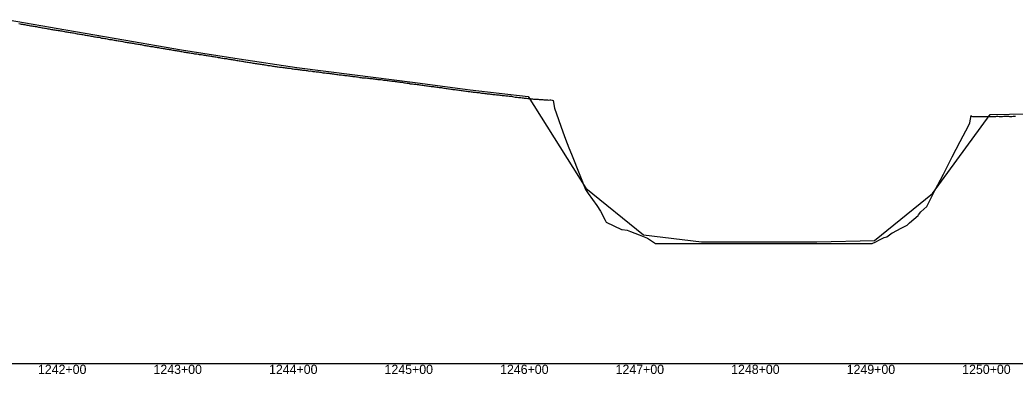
# Model space of a CAD drawing. Extents: x -3793 to 50787, y -1075 to 6138.
# Drawn here: x 11538 to 12399, y 2991 to 3298 of the extents above; entities that cross this region are included whole.
import ezdxf

# ---------------------------------------------------------------- set-up
doc = ezdxf.new("R2010")
doc.units = 0
for name, color, linetype in [('RD_DDB_Profile_EX', 7, 'Continuous'), ('RD_DDB_Profile_PR', 7, 'Continuous'), ('RD_DDB_StaTX', 7, 'Continuous'), ('RD_GPK_Profile_Cell', 7, 'Continuous')]:
    doc.layers.add(name, color=color, linetype=linetype)

msp = doc.modelspace()

# ---------------------------------------------------------------- linework, layer by layer
at = {"layer": 'RD_DDB_Profile_EX'}
for points in [[(11536.652242, 3294.36991), (11537.652092, 3294.15), (11538.655829, 3293.91986), (11539.653933, 3293.79005), (11540.652812, 3293.67002), (11541.654813, 3293.529805), (11542.647632, 3293.279725), (11543.645738, 3293.1), (11544.645586, 3292.95), (11545.649322, 3292.8), (11546.647428, 3292.579775), (11547.725313, 3292.45997), (11548.728588, 3292.21982), (11549.728712, 3292.11989), (11550.72806, 3291.910005), (11551.726314, 3291.729955), (11552.728804, 3291.60999), (11553.728931, 3291.429955), (11554.728272, 3291.23992), (11555.719036, 3291.03996), (11556.721522, 3290.82999), (11557.721653, 3290.66988), (11558.719903, 3290.5), (11559.722391, 3290.320045), (11560.72252, 3290.06035), (11561.721859, 3289.980345), (11562.720098, 3289.9), (11563.722584, 3289.6404), (11564.722715, 3289.4), (11565.722048, 3289.31019), (11566.720278, 3289.09084), (11567.723568, 3288.90076), (11568.715444, 3288.81015), (11569.713679, 3288.75), (11570.716163, 3288.480405), (11571.716296, 3288.340675), (11572.715628, 3288.1409), (11573.713853, 3287.990975), (11574.716335, 3287.78979), (11576.009865, 3287.46152), (11577.002754, 3287.35114), (11578.003685, 3287.230535), (11579.007399, 3287.070245), (11579.999286, 3286.93036), (11581.001219, 3286.78014), (11582.000125, 3286.57021), (11583.003839, 3286.38014), (11583.999548, 3286.239815), (11584.997659, 3286.12992), (11586.001373, 3285.86983), (11587.00028, 3285.65997), (11587.996928, 3285.56971), (11588.9941, 3285.24949), (11589.997814, 3285.08936), (11590.993506, 3284.97924), (11591.991634, 3284.81953), (11592.994412, 3284.688925), (11593.994254, 3284.429295), (11594.990866, 3284.3), (11595.991959, 3284.0096), (11596.991788, 3283.959635), (11597.987464, 3283.728615), (11598.987293, 3283.6), (11599.988407, 3283.46905), (11600.999406, 3283.3), (11601.993282, 3282.997275), (11602.996052, 3282.928255), (11603.995902, 3282.640545), (11604.998672, 3282.60942), (11605.99131, 3282.487575), (11606.99408, 3282.28743), (11607.995203, 3281.83723), (11608.987813, 3281.78713), (11609.990596, 3281.686985), (11610.990433, 3281.514975), (11611.993217, 3281.436985), (11612.984945, 3281.155455), (11613.988588, 3280.91837), (11614.989754, 3280.727405), (11615.989577, 3280.62751), (11616.985112, 3280.55), (11617.984083, 3280.27739), (11618.987732, 3280.14093), (11619.98325, 3279.92692), (11620.491182, 3279.8138)], [(11620.491182, 3279.8138), (11621.485517, 3279.705245), (11622.485183, 3279.522975), (11623.485443, 3279.41809), (11624.487798, 3279.29099), (11625.488058, 3279.1), (11626.480621, 3278.891065), (11627.480287, 3278.62697), (11628.483236, 3278.40893), (11629.482902, 3278.28202), (11630.48585, 3278.05893), (11631.477474, 3278), (11632.475392, 3277.767945), (11633.47834, 3277.658915), (11634.478006, 3277.45), (11635.480954, 3277.3), (11636.48062, 3277.15897), (11637.474933, 3276.976615), (11638.473444, 3276.8), (11639.475811, 3276.65886), (11640.476058, 3276.508895), (11641.478425, 3276.35), (11642.470035, 3276.14688), (11643.470289, 3275.9), (11644.470916, 3275.73536), (11645.471163, 3275.541125), (11646.425702, 3275.4), (11647.424086, 3275.258845), (11648.418672, 3275.126075), (11649.417069, 3274.873855), (11650.420344, 3274.682685), (11651.419426, 3274.55), (11652.421093, 3274.441405), (11653.411748, 3274.28289), (11654.410832, 3274.05856), (11655.414116, 3273.91701), (11656.413202, 3273.71702), (11657.414909, 3273.60844), (11658.405557, 3273.458405), (11659.407955, 3273.10832), (11660.407939, 3273.05), (11661.409684, 3272.85829), (11662.408773, 3272.68341), (11663.241396, 3272.55834), (11663.748903, 3272.508235), (11664.742062, 3272.35), (11665.744382, 3272.174375), (11666.742619, 3271.94185), (11667.745755, 3271.858065), (11668.740776, 3271.71588), (11669.740418, 3271.515955), (11670.743565, 3271.342105), (11671.741818, 3271.2), (11672.737609, 3270.97666), (11673.735871, 3270.842195), (11674.739634, 3270.66899), (11675.742809, 3270.561645), (11676.733682, 3270.254165), (11677.73612, 3270.131825), (11678.735139, 3270.05449), (11679.738909, 3269.76987), (11680.730504, 3269.675155), (11681.732966, 3269.39805), (11682.73545, 3269.333775), (11683.728297, 3269.09875), (11684.730786, 3268.984665), (11685.729083, 3268.86985), (11686.732307, 3268.699535), (11687.723139, 3268.442325), (11688.727609, 3268.26466), (11689.730143, 3268.1295), (11690.728453, 3268.079225), (11691.724199, 3267.951385), (11692.722517, 3267.74422), (11693.726294, 3267.63079), (11694.725297, 3267.523725), (11695.735083, 3267.268225), (11696.738749, 3267.0756), (11697.737703, 3266.96823), (11698.741369, 3266.73913), (11699.73146, 3266.652765), (11700.735125, 3266.52991), (11701.73408, 3266.336505), (11702.730059, 3266.1), (11703.212794, 3266.086715), (11704.215852, 3265.9), (11705.215409, 3265.830075), (11706.210078, 3265.65427), (11707.208375, 3265.517125), (11708.211433, 3265.273905), (11709.21145, 3265.123755), (11710.205647, 3264.93707), (11711.208694, 3264.743585), (11712.207014, 3264.587085), (11713.201647, 3264.430955), (11714.201215, 3264.2372), (11715.204263, 3264.17461), (11716.202595, 3264.02444), (11717.197216, 3263.831155), (11718.199829, 3263.587515), (11719.199831, 3263.48744)], [(11719.199831, 3263.48744), (11720.192787, 3263.33765), (11721.192784, 3263.18136), (11722.195402, 3262.969125), (11723.195399, 3262.887575), (11724.18836, 3262.64389), (11725.191411, 3262.5), (11726.190975, 3262.44389), (11727.194026, 3262.251545), (11728.183933, 3262.069795), (11729.186984, 3261.88203), (11730.186548, 3261.78792), (11731.181087, 3261.626275), (11732.18372, 3261.376435), (11733.182557, 3261.18223), (11734.185608, 3261.026515), (11735.176647, 3260.88241), (11736.179689, 3260.738375), (11737.181215, 3260.621175), (11738.172633, 3260.421275), (11739.175279, 3260.215765), (11740.175249, 3260.071275), (11741.176793, 3259.838605), (11742.168193, 3259.72729), (11743.170844, 3259.627445), (11744.257976, 3259.45517), (11745.25965, 3259.311105), (11746.254321, 3259.17822), (11747.25707, 3258.983785), (11748.251699, 3258.83412), (11749.244917, 3258.67926), (11750.186584, 3258.54486), (11751.182493, 3258.37989), (11752.185762, 3258.24003), (11753.181158, 3258.1), (11754.189346, 3257.995265), (11755.184726, 3257.84537), (11756.188035, 3257.627055), (11757.183844, 3257.47763), (11758.179187, 3257.336895), (11759.182516, 3257.195675), (11760.17785, 3256.995785), (11761.181601, 3256.94167), (11762.176205, 3256.78785), (11763.179569, 3256.64199), (11764.175272, 3256.530555), (11765.170566, 3256.388665), (11766.17395, 3256.242535), (11767.169587, 3256.1), (11768.172984, 3255.989295), (11769.168246, 3255.796545), (11770.171991, 3255.73979), (11771.167232, 3255.68684), (11772.170658, 3255.49027), (11773.166192, 3255.290635), (11774.160866, 3255.187985), (11775.164321, 3254.99409), (11776.16413, 3254.93906), (11777.167879, 3254.88928), (11778.16307, 3254.69231), (11779.16657, 3254.54246), (11780.161983, 3254.35), (11781.165496, 3254.29532), (11782.160653, 3254.19556), (11783.155995, 3254.041625), (11784.159529, 3253.9857), (11785.154644, 3253.792315), (11786.158049, 3253.64255), (11787.153162, 3253.44652), (11788.156736, 3253.29494), (11789.151989, 3253.339085), (11790.155577, 3253.190965), (11791.150655, 3253.043095), (11792.145712, 3252.94498), (11792.82433, 3252.842925), (11793.823599, 3252.74382), (11794.826851, 3252.642915), (11795.821132, 3252.543695), (11796.824393, 3252.44303), (11797.814388, 3252.19315), (11798.811602, 3251.94908), (11799.815098, 3251.8), (11800.805443, 3251.797465), (11801.809036, 3251.74528), (11802.812777, 3251.595625), (11803.807857, 3251.44581), (11804.806695, 3251.394775), (11805.810373, 3251.147015), (11806.805347, 3251.04814), (11807.804278, 3250.947395), (11808.807932, 3250.79676), (11809.802975, 3250.698005), (11810.80671, 3250.49835), (11811.80557, 3250.298675), (11812.800558, 3250.2488), (11813.804268, 3250.14857), (11814.803163, 3250.04821), (11815.798135, 3249.94966), (11816.994233, 3249.771255), (11817.805974, 3249.649865), (11818.796227, 3249.549815)], [(11818.796227, 3249.549815), (11819.800405, 3249.499605), (11820.80459, 3249.34936), (11821.794854, 3249.199295), (11822.79903, 3249.049255), (11823.795047, 3248.898995), (11824.799213, 3248.798845), (11825.797665, 3248.64899), (11826.793666, 3248.54848), (11827.797855, 3248.44831), (11828.796282, 3248.348645), (11829.792316, 3248.198515), (11830.796442, 3248.04838), (11831.794906, 3247.848725), (11832.790946, 3247.798465), (11833.795092, 3247.549175), (11834.36085, 3247.54765), (11835.357229, 3247.497645), (11836.353668, 3247.397345), (11837.357961, 3247.34641), (11838.354411, 3247.09735), (11839.358694, 3246.997235), (11840.355153, 3246.946475), (11841.361477, 3246.845825), (11842.358115, 3246.74548), (11843.342564, 3246.54757), (11844.365169, 3246.49602), (11845.347652, 3246.2), (11846.366163, 3246.147105), (11847.347437, 3246.04847), (11848.367037, 3245.94529), (11849.363708, 3245.89338), (11850.342922, 3245.84391), (11851.346976, 3245.646445), (11852.36126, 3245.495345), (11853.346619, 3245.39715), (11854.342365, 3245.345045), (11855.366538, 3245.14495), (11856.347474, 3244.997825), (11857.373629, 3244.89225), (11858.37035, 3244.793105), (11859.343165, 3244.64643), (11860.371172, 3244.49637), (11861.342779, 3244.39875), (11862.372179, 3244.29746), (11863.368721, 3244.196065), (11864.346432, 3244.05), (11865.369733, 3243.895885), (11866.338123, 3243.701415), (11867.370524, 3243.647135), (11868.343031, 3243.55), (11869.347083, 3243.348475), (11870.34286, 3243.203135), (11871.378522, 3243.148415), (11872.342602, 3242.7614), (11873.338387, 3242.758345), (11874.342441, 3242.708435), (11875.372662, 3242.308645), (11876.377085, 3242.348255), (11877.337981, 3242.155365), (11878.378105, 3241.86806), (11879.38063, 3241.866955), (11880.338809, 3241.86732), (11881.366232, 3241.5711), (11882.37043, 3241.56743), (11883.374308, 3241.37152), (11884.365105, 3241.223545), (11885.368981, 3241.071795), (11886.372947, 3240.971985), (11887.369296, 3240.92244), (11888.367626, 3240.82024), (11889.371823, 3240.56634), (11890.367843, 3240.46251), (11891.36627, 3240.318595), (11892.370467, 3240.17502), (11893.366487, 3240.025525), (11894.370684, 3239.9236), (11895.369009, 3239.7713), (11896.365132, 3239.619525), (11897.369329, 3239.517505), (11898.359833, 3239.41756), (11899.364032, 3239.315495), (11900.367866, 3239.120095), (11901.363993, 3238.970455), (11902.362681, 3238.91579), (11903.366508, 3238.672755), (11904.362905, 3238.475485), (11905.366722, 3238.371025), (11906.365151, 3238.266225), (11907.361555, 3238.17123), (11908.365365, 3238.023785), (11909.364066, 3237.82362), (11910.360089, 3237.719235), (11911.364008, 3237.61937), (11912.367804, 3237.419525), (11913.358736, 3237.372025), (11914.362934, 3237.26726), (11915.358957, 3237.120065), (11916.357384, 3236.972405), (11917.361172, 3236.7276), (11918.357605, 3236.675505)], [(11918.357605, 3236.675505), (11919.376738, 3236.5308), (11920.375363, 3236.3255), (11921.371743, 3236.18107), (11922.37574, 3236.17345), (11923.374369, 3235.981075), (11924.370752, 3235.78417), (11925.374744, 3235.72645), (11925.971078, 3235.63158), (11926.966969, 3235.529375), (11927.96581, 3235.38185), (11928.969593, 3235.274035), (11929.96814, 3235.126525), (11930.971476, 3235.03471), (11931.96766, 3234.882535), (11932.966209, 3234.72962), (11933.969984, 3234.67709), (11934.968833, 3234.582315), (11935.964725, 3234.34371), (11936.963273, 3234.10156), (11937.967047, 3234.09641), (11938.97112, 3233.99947), (11939.96967, 3233.88276), (11940.965563, 3233.7443), (11941.964112, 3233.64951), (11942.968186, 3233.45261), (11943.966735, 3233.446765), (11944.970504, 3233.24704), (11945.961486, 3233.188825), (11946.965255, 3233.047425), (11947.96902, 3233.04209), (11948.967105, 3232.98347), (11949.963307, 3232.792445), (11950.961857, 3232.694985), (11951.965618, 3232.645245), (11952.96417, 3232.40338), (11953.968241, 3232.33959), (11954.964135, 3232.23726), (11955.962686, 3232.18418), (11956.966759, 3232.034395), (11957.96531, 3231.889875), (11958.969066, 3231.74583), (11959.959757, 3231.6959), (11960.96383, 3231.643305), (11961.962381, 3231.54303), (11962.966135, 3231.431735), (11963.962031, 3231.282145), (11965.054879, 3230.85863), (11966.112042, 3230.705265), (11967.049786, 3230.658915), (11968.053504, 3230.562145), (11969.057219, 3230.412435), (11970.048418, 3230.31244), (11971.052134, 3230.256745), (11972.115642, 3230.15988), (11973.051684, 3230.019605), (11974.050264, 3229.869035), (11975.114543, 3229.76917), (11976.050319, 3229.722955), (11977.048897, 3229.619345), (11978.280805, 3229.543715), (11979.048447, 3229.46712), (11980.052665, 3229.320235), (11981.051242, 3229.222585), (11982.046751, 3229.076205), (11983.050458, 3228.920205), (11984.054164, 3228.873355), (11985.044878, 3228.91708), (11985.598014, 3228.88961), (11986.049096, 3228.87319), (11987.052804, 3228.71708), (11988.056512, 3228.67012), (11989.047226, 3228.57288), (11990.050936, 3228.52287), (11991.115713, 3228.38187), (11992.050995, 3228.3825), (11993.049576, 3228.32553), (11994.113482, 3228.37836), (11995.049131, 3228.14402), (11996.053352, 3228.24382), (11997.111568, 3228.32166), (11998.107797, 3228.192215), (11999.092864, 3227.84066), (12000.232434, 3221.21318), (12007.549644, 3200.72147), (12009.852719, 3194.2719), (12012.74671, 3186.77351), (12014.866853, 3181.44025), (12022.184063, 3163.032595), (12027.023819, 3150.856695), (12029.501273, 3147.291335), (12036.818483, 3136.760165), (12040.159552, 3131.95123), (12044.135692, 3124.158525), (12045.05235, 3122.38407), (12051.452902, 3119.29524), (12058.188175, 3116.04544), (12058.770112, 3115.98718), (12063.079715, 3115.55677), (12066.087322, 3114.361955), (12073.404531, 3111.454815)], [(12073.404531, 3111.454815), (12080.792382, 3108.519355), (12087.569175, 3103.95), (12088.038951, 3103.95), (12088.911974, 3103.95), (12093.575737, 3103.95), (12094.488472, 3103.95), (12095.356161, 3103.95), (12102.67337, 3103.95), (12107.565722, 3103.95), (12109.99058, 3103.95), (12117.30779, 3103.95), (12124.625, 3103.95), (12131.942209, 3103.95), (12139.259419, 3103.95), (12146.576629, 3103.95), (12153.893839, 3103.95), (12161.211048, 3103.95), (12168.528258, 3103.95), (12175.845468, 3103.95), (12183.162678, 3103.95), (12190.479887, 3103.95), (12197.797097, 3103.95), (12205.114307, 3103.95), (12212.431517, 3103.95), (12219.748726, 3103.95), (12227.065936, 3103.95), (12234.383146, 3103.95), (12235.095961, 3103.95), (12241.700356, 3103.95), (12249.017566, 3103.95), (12256.334775, 3103.95), (12263.651985, 3103.95), (12270.969195, 3103.95), (12275.22801, 3103.95), (12278.286405, 3105.501115), (12281.555999, 3107.16006), (12285.711233, 3109.05109), (12287.94298, 3109.62094), (12292.581701, 3113.088695), (12292.920824, 3113.267345), (12300.238034, 3117.123625), (12305.482142, 3119.888535), (12307.555244, 3121.735095), (12314.872453, 3128.25292), (12315.357578, 3128.685065), (12317.396575, 3131.313705), (12322.392704, 3135.903065), (12329.506873, 3149.814835), (12336.824083, 3164.12391), (12344.141292, 3178.43322), (12344.483747, 3179.102925), (12351.49971, 3192.330345), (12358.775712, 3206.312755), (12359.818314, 3208.3163), (12360.925095, 3214.820055), (12361.044836, 3214.11483), (12362.092902, 3214.072145), (12363.051072, 3214.072265), (12364.095029, 3214.0708), (12365.052967, 3214.02273), (12366.092922, 3214.016505), (12367.091436, 3214.065685), (12368.085717, 3213.969245), (12369.056986, 3213.921345), (12370.0511, 3213.971205), (12371.089265, 3213.96835), (12372.05322, 3213.96952), (12373.091223, 3214.004035), (12373.410131, 3213.988405), (12374.05513, 3213.956705), (12375.093042, 3213.918255), (12376.087238, 3213.918), (12377.051385, 3213.967185), (12378.089031, 3214.01597), (12379.053305, 3214.016945), (12380.055428, 3214.0176), (12381.084722, 3214.018995), (12382.092476, 3214.067115), (12383.086358, 3214.11489), (12384.086787, 3214.11211), (12385.088225, 3214.06263), (12386.082105, 3214.012185), (12387.089866, 3213.963805), (12388.083968, 3214.063385), (12389.057462, 3214.111455), (12390.085453, 3214.212495), (12391.092919, 3214.212185), (12392.156326, 3214.21107), (12393.156648, 3214.215005), (12394.156751, 3214.072325), (12395.361761, 3214.071605), (12396.15844, 3214.074505), (12397.158473, 3214.126655), (12398.152446, 3214.175745), (12399.160078, 3214.27357)]]:
    msp.add_lwpolyline(points, dxfattribs=at)
at = {"layer": 'RD_DDB_Profile_PR'}
msp.add_lwpolyline([(11527.33, 3297.583), (11577.33, 3288.9115), (11627.33, 3280.2665), (11677.33, 3271.7815), (11727.33, 3263.8265), (11777.33, 3256.457), (11827.33, 3250.095), (11877.33, 3243.757), (11927.33, 3237.076), (11977.33, 3231.202), (12027.33, 3152.016), (12077.33, 3111.495), (12127.33, 3105.55), (12177.33, 3105.55), (12227.33, 3105.55), (12277.33, 3106.616), (12327.33, 3147.158), (12377.33, 3215.5805), (12427.33, 3216.5915)], dxfattribs=at)
at = {"layer": 'RD_GPK_Profile_Cell'}
msp.add_line((1000, 3000), (46549.603806, 3000), dxfattribs=at)

# ---------------------------------------------------------------- texts
at = {"layer": 'RD_DDB_StaTX'}
for s, p in [('1242+00', (11553.125471, 2991)), ('1242+00', (11553.125471, 2991)), ('1243+00', (11653.125471, 2991)), ('1243+00', (11653.125471, 2991)), ('1244+00', (11753.125471, 2991)), ('1244+00', (11753.125471, 2991)), ('1245+00', (11853.125471, 2991)), ('1245+00', (11853.125471, 2991)), ('1246+00', (11953.125471, 2991)), ('1246+00', (11953.125471, 2991)), ('1247+00', (12053.125471, 2991)), ('1247+00', (12053.125471, 2991)), ('1248+00', (12153.125471, 2991)), ('1248+00', (12153.125471, 2991)), ('1249+00', (12253.125471, 2991)), ('1249+00', (12253.125471, 2991)), ('1250+00', (12353.125471, 2991)), ('1250+00', (12353.125471, 2991))]:
    msp.add_text(s, height=8, dxfattribs=at).set_placement(p)

doc.saveas('drawing.dxf')
